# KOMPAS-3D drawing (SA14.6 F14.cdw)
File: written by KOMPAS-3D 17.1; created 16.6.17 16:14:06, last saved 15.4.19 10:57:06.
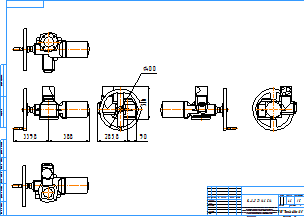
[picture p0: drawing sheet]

Sheet 1: A2, landscape

Title block, sheet 1: name: Привод SA 14.6 F14; material: Внимание! Данный продукт является объектом авторского права ООО «Торговый Дом АДЛ». / Запрещается изменение, копирование, распространение / (в том числе путем копирования на другие сайты и ресурсы в Интернете) / или любое иное использование информации и объектов без предварительного / согласия правообладателя (ООО «Торговый Дом АДЛ»).; mass: 46; sheets: 1; organisation: ООО "Торговый дом АДЛ"; sheet format: A2; stored path: \\adlc.lan\data\АДЛ_ПКД\3D-модели\Поставщики\Сервоприводы AUMA\Электроприводы серии SA\KOMPAS 2D\Привод SA 14.6 F14.cdw

Views: Спереди 1, Проекционный вид 2, Проекционный вид 3, Проекционный вид 4, Проекционный вид 5, Проекционный вид 6
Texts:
  Klimkovich
  ADL
Dimensions and other numbers on the sheet: 316; 90; 285,8; 400; 388; 339,8; 1:5; 1; 46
